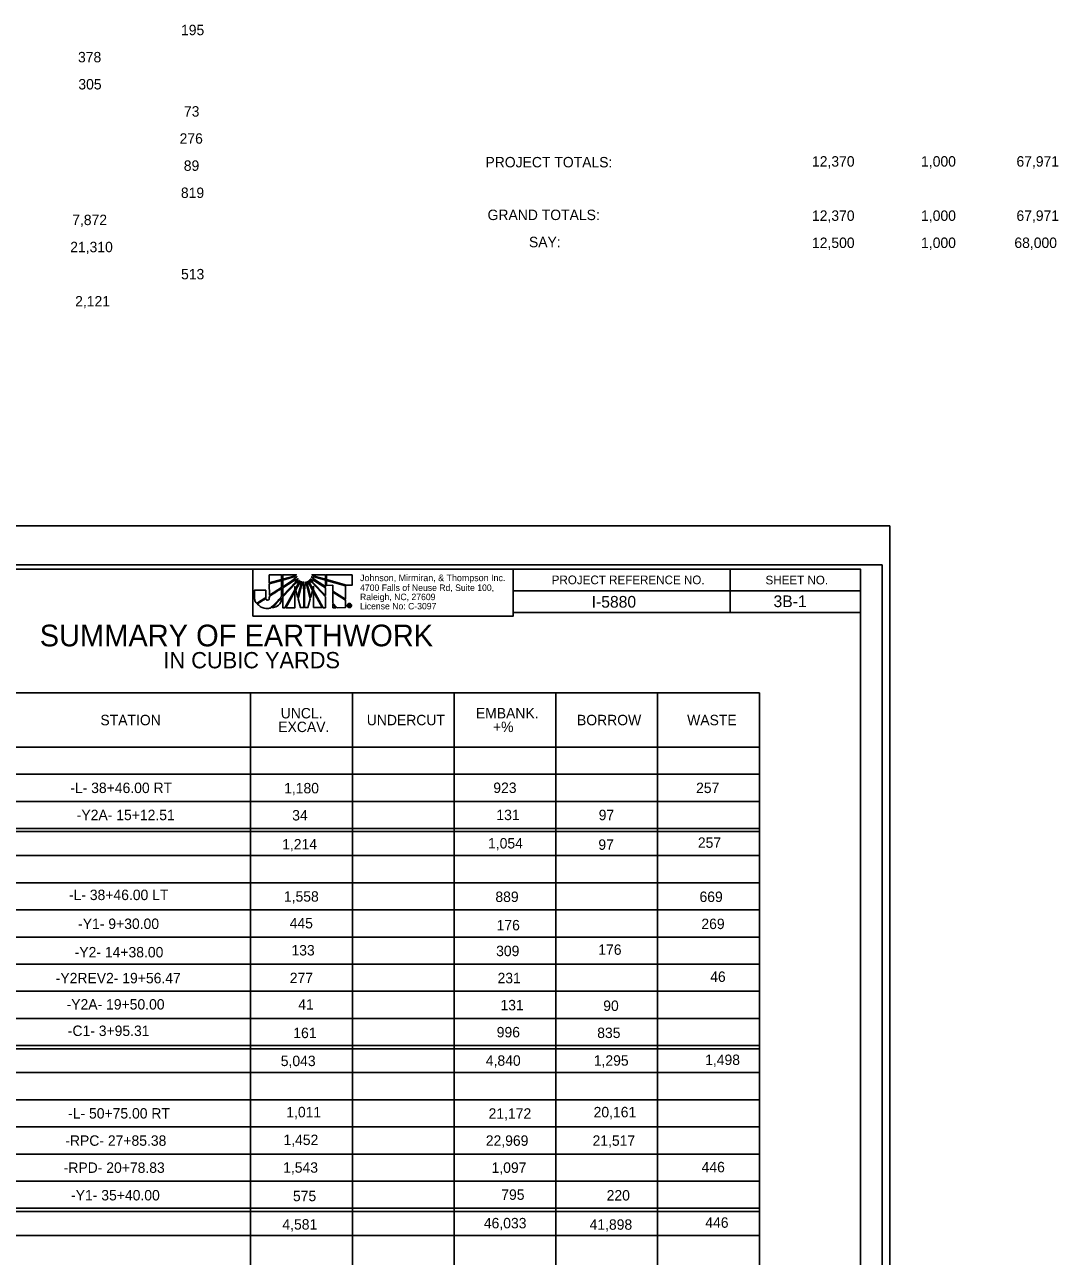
# Model space of a CAD drawing. Extents: x 573692 to 577281, y -53325 to -51406.
# Drawn here: x 574877 to 575473, y -52643 to -51934 of the extents above; entities that cross this region are included whole.
import ezdxf

# ---------------------------------------------------------------- set-up
doc = ezdxf.new("R2010")
doc.units = 0
for name, color, linetype in [('Exist Profile Cell', 7, 'Continuous'), ('Exist Vertical Profile Ground Line', 7, 'Continuous'), ('Prop Conc Island Cover', 7, 'Continuous'), ('Prop EOT', 7, 'Continuous'), ('Prop Horizontal Alignment', 7, 'Continuous'), ('Sheet North Arrow CELL', 7, 'Continuous')]:
    doc.layers.add(name, color=color, linetype=linetype)

msp = doc.modelspace()

# ---------------------------------------------------------------- linework, layer by layer
at = {"layer": 'Exist Profile Cell'}
msp.add_lwpolyline([(575375.82, -52222.48), (573691.82, -52222.48), (573691.82, -53322.48), (575375.82, -53322.48)], close=True, dxfattribs=at)
at = {"layer": 'Prop Conc Island Cover'}
msp.add_lwpolyline([(575371.32, -52244.93), (573704.82, -52244.93), (573704.82, -53300.03), (575371.32, -53300.03)], close=True, dxfattribs=at)
at = {"layer": 'Prop EOT'}
for p, q in [((575283.82, -52247.53), (575283.82, -52272.53)), ((575158.77, -52260.03), (575358.82, -52260.03)), ((575158.77, -52272.53), (575358.82, -52272.53)), ((574968.75, -52318.72), (574968.75, -52318.72)), ((574949.63, -52318.85), (574949.63, -52318.85)), ((574957.44, -52318.97), (574957.44, -52318.97)), ((574975.75, -52318.85), (574975.75, -52318.85))]:
    msp.add_line(p, q, dxfattribs=at)
for points in [[(575358.82, -52247.48), (573858.82, -52247.48), (573858.82, -53297.48), (575358.82, -53297.48)], [(575158.77, -52247.48), (575358.82, -52247.48), (575358.82, -52272.53), (575158.77, -52272.53)]]:
    msp.add_lwpolyline(points, close=True, dxfattribs=at)
at = {"layer": 'Prop Horizontal Alignment'}
for p, q in [((575025.33, -52250.8), (575018.31, -52250.8)), ((575018.31, -52250.8), (575018.31, -52255.46)), ((575018.31, -52255.46), (575025.33, -52253.51)), ((575025.33, -52254.02), (575018.31, -52255.99)), ((575025.33, -52253.51), (575025.33, -52250.8)), ((575025.33, -52258.08), (575025.33, -52254.02)), ((575033.95, -52250.75), (575026.06, -52250.76)), ((575026.06, -52250.76), (575026.06, -52253.27)), ((575026.06, -52253.27), (575031.94, -52251.65)), ((575031.94, -52252.19), (575026.06, -52253.82)), ((575026.06, -52253.82), (575026.06, -52257.62)), ((575026.06, -52257.62), (575031.33, -52254.28)), ((575032.14, -52254.36), (575026.06, -52258.23)), ((575026.07, -52262.61), (575033.46, -52254.9)), ((575031.33, -52254.28), (575034.23, -52251.91)), ((575031.94, -52251.65), (575033.95, -52250.75)), ((575034.23, -52251.91), (575031.94, -52252.19)), ((575034.81, -52253), (575032.14, -52254.36)), ((575033.46, -52254.9), (575034.81, -52253)), ((575035.62, -52253.84), (575033.76, -52255.28)), ((575034.77, -52256.09), (575035.62, -52253.84)), ((575036.63, -52254.47), (575035.24, -52256.25)), ((575036.44, -52256.63), (575036.63, -52254.47)), ((575037.79, -52254.78), (575036.83, -52257.03)), ((575038.1, -52260.32), (575037.79, -52254.78)), ((575038.95, -52254.78), (575038.6, -52260.31)), ((575039.88, -52257.02), (575038.95, -52254.78)), ((575040.07, -52254.47), (575040.31, -52256.71)), ((575041.43, -52256.25), (575040.07, -52254.47)), ((575041.07, -52253.84), (575041.93, -52256.08)), ((575042.93, -52255.27), (575041.07, -52253.84)), ((575041.89, -52252.99), (575043.25, -52254.93)), ((575044.6, -52254.35), (575041.89, -52252.99)), ((575042.5, -52251.9), (575045.44, -52254.31)), ((575044.67, -52252.18), (575042.5, -52251.9)), ((575050.68, -52250.77), (575042.89, -52250.75)), ((575042.89, -52250.75), (575044.86, -52251.67)), ((575043.25, -52254.93), (575050.64, -52262.67)), ((575050.64, -52258.17), (575044.6, -52254.35)), ((575050.68, -52253.83), (575044.67, -52252.18)), ((575044.86, -52251.67), (575050.68, -52253.3)), ((575045.44, -52254.31), (575050.64, -52257.55)), ((575050.64, -52257.55), (575050.68, -52253.83)), ((575050.68, -52253.3), (575050.68, -52250.77)), ((575065.97, -52250.72), (575051.22, -52250.74)), ((575051.22, -52250.74), (575051.22, -52253.45)), ((575051.22, -52253.45), (575051.22, -52253.53)), ((575051.22, -52253.53), (575062.84, -52256.77)), ((575051.22, -52253.95), (575051.22, -52253.99)), ((575062.1, -52257.04), (575051.22, -52253.95)), ((575051.22, -52253.99), (575051.23, -52256.82)), ((575065.98, -52256.77), (575065.97, -52250.72)), ((575018.31, -52255.99), (575018.32, -52262.53)), ((575018.32, -52262.53), (575025.33, -52258.08)), ((575026.06, -52258.23), (575026.07, -52262.61)), ((575033.76, -52255.28), (575026.07, -52263.35)), ((575027.23, -52269.72), (575032.95, -52259.35)), ((575032.96, -52260.35), (575027.78, -52269.72)), ((575032.95, -52259.35), (575032.95, -52257.49)), ((575032.95, -52257.49), (575033.3, -52258.77)), ((575033.01, -52269.71), (575032.96, -52260.35)), ((575033.3, -52258.77), (575034.77, -52256.09)), ((575035.24, -52256.25), (575033.5, -52259.43)), ((575033.5, -52259.43), (575034.63, -52263.64)), ((575034.63, -52263.64), (575036.44, -52256.63)), ((575036.83, -52257.03), (575034.86, -52264.61)), ((575038.11, -52269.67), (575038.1, -52260.32)), ((575038.6, -52260.31), (575038.6, -52269.67)), ((575041.9, -52264.72), (575039.88, -52257.02)), ((575040.31, -52256.71), (575042.13, -52263.8)), ((575043.25, -52259.53), (575041.43, -52256.25)), ((575041.93, -52256.08), (575043.43, -52258.87)), ((575042.13, -52263.8), (575043.25, -52259.53)), ((575050.64, -52263.39), (575042.93, -52255.27)), ((575043.43, -52258.87), (575043.79, -52257.48)), ((575043.79, -52257.48), (575043.79, -52259.53)), ((575043.79, -52259.53), (575049.41, -52269.7)), ((575048.83, -52269.66), (575043.79, -52260.54)), ((575043.79, -52260.54), (575043.8, -52269.67)), ((575050.64, -52262.67), (575050.64, -52258.17)), ((575051.23, -52256.82), (575054.83, -52256.81)), ((575054.83, -52256.81), (575054.83, -52260.18)), ((575054.83, -52260.18), (575062.11, -52264.79)), ((575054.83, -52260.76), (575054.84, -52267.04)), ((575062.11, -52265.33), (575054.83, -52260.76)), ((575062.11, -52264.79), (575062.1, -52257.04)), ((575062.84, -52256.77), (575065.98, -52256.77)), ((575026.07, -52263.35), (575026.07, -52269.72)), ((575034.86, -52264.61), (575036.18, -52269.67)), ((575040.55, -52269.67), (575041.9, -52264.72)), ((575050.65, -52269.69), (575050.64, -52263.39)), ((575054.84, -52267.04), (575057.35, -52269.69)), ((575056.66, -52269.69), (575054.84, -52267.72)), ((575054.84, -52267.72), (575054.84, -52269.69)), ((575062.11, -52269.68), (575062.11, -52265.33)), ((575063.96, -52269.02), (575063.96, -52267.95)), ((575063.96, -52267.95), (575064.4, -52267.95)), ((575064.2, -52269.02), (575063.96, -52269.02)), ((575064.4, -52268.15), (575064.2, -52268.15)), ((575064.2, -52268.15), (575064.2, -52268.4)), ((575064.2, -52268.4), (575064.4, -52268.4)), ((575064.4, -52268.6), (575064.2, -52268.6)), ((575064.2, -52268.6), (575064.2, -52269.02)), ((575064.4, -52267.31), (575064.4, -52267.54)), ((575064.4, -52267.54), (575064.4, -52267.31)), ((575064.4, -52267.95), (575064.4, -52268.15)), ((575064.4, -52268.15), (575064.4, -52267.95)), ((575064.4, -52267.95), (575064.46, -52267.95)), ((575064.43, -52268.15), (575064.4, -52268.15)), ((575064.4, -52268.4), (575064.4, -52268.6)), ((575064.4, -52268.6), (575064.4, -52268.4)), ((575064.4, -52268.4), (575064.41, -52268.4)), ((575064.41, -52268.6), (575064.4, -52268.6)), ((575026.07, -52269.72), (575027.23, -52269.72)), ((575027.78, -52269.72), (575033.01, -52269.71)), ((575036.18, -52269.67), (575038.11, -52269.67)), ((575038.6, -52269.67), (575040.55, -52269.67)), ((575043.8, -52269.67), (575048.83, -52269.66)), ((575049.41, -52269.7), (575050.65, -52269.69)), ((575054.84, -52269.69), (575056.66, -52269.69)), ((575057.35, -52269.69), (575062.11, -52269.68)), ((575064.4, -52269.44), (575064.4, -52269.67)), ((575064.4, -52269.67), (575064.4, -52269.44)), ((575064.4, -52269.44), (575064.41, -52269.44)), ((575064.41, -52269.67), (575064.4, -52269.67))]:
    msp.add_line(p, q, dxfattribs=at)
msp.add_lwpolyline([(575008.82, -52274.54), (575158.77, -52274.54), (575158.77, -52247.48), (575008.82, -52247.48)], close=True, dxfattribs=at)
for points in [[(575018.31, -52255.46), (575025.33, -52253.51), (575025.33, -52250.8), (575018.31, -52250.8), (575018.31, -52255.46)], [(575018.32, -52262.53), (575025.33, -52258.08), (575025.33, -52254.02), (575018.31, -52255.99), (575018.32, -52262.53)], [(575031.94, -52251.65), (575033.95, -52250.75), (575026.06, -52250.76), (575026.06, -52253.27), (575031.94, -52251.65)], [(575026.06, -52253.82), (575026.06, -52257.62), (575031.33, -52254.28), (575034.23, -52251.91), (575031.94, -52252.19), (575026.06, -52253.82)], [(575026.06, -52258.23), (575026.07, -52262.61), (575033.46, -52254.9), (575034.81, -52253), (575032.14, -52254.36), (575026.06, -52258.23)], [(575035.62, -52253.84), (575033.76, -52255.28), (575026.07, -52263.35), (575026.07, -52269.72), (575027.23, -52269.72), (575032.95, -52259.35), (575032.95, -52257.49), (575033.3, -52258.77), (575034.77, -52256.09), (575035.62, -52253.84)], [(575036.63, -52254.47), (575035.24, -52256.25), (575033.5, -52259.43), (575034.63, -52263.64), (575036.44, -52256.63), (575036.63, -52254.47)], [(575036.83, -52257.03), (575034.86, -52264.61), (575036.18, -52269.67), (575038.11, -52269.67), (575038.1, -52260.32), (575037.79, -52254.78), (575036.83, -52257.03)], [(575038.95, -52254.78), (575038.6, -52260.31), (575038.6, -52269.67), (575040.55, -52269.67), (575041.9, -52264.72), (575039.88, -52257.02), (575038.95, -52254.78)], [(575040.07, -52254.47), (575040.31, -52256.71), (575042.13, -52263.8), (575043.25, -52259.53), (575041.43, -52256.25), (575040.07, -52254.47)], [(575041.07, -52253.84), (575041.93, -52256.08), (575043.43, -52258.87), (575043.79, -52257.48), (575043.79, -52259.53), (575049.41, -52269.7), (575050.65, -52269.69), (575050.64, -52263.39), (575042.93, -52255.27), (575041.07, -52253.84)], [(575041.89, -52252.99), (575043.25, -52254.93), (575050.64, -52262.67), (575050.64, -52258.17), (575044.6, -52254.35), (575041.89, -52252.99)], [(575042.5, -52251.9), (575045.44, -52254.31), (575050.64, -52257.55), (575050.68, -52253.83), (575044.67, -52252.18), (575042.5, -52251.9)], [(575044.86, -52251.67), (575050.68, -52253.3), (575050.68, -52250.77), (575042.89, -52250.75), (575044.86, -52251.67)], [(575065.97, -52250.72), (575051.22, -52250.74), (575051.22, -52253.45), (575051.22, -52253.53), (575062.84, -52256.77), (575065.98, -52256.77), (575065.97, -52250.72)], [(575051.22, -52253.95), (575051.22, -52253.99), (575051.23, -52256.82), (575054.83, -52256.81), (575054.83, -52260.18), (575062.11, -52264.79), (575062.1, -52257.04), (575051.22, -52253.95)], [(575027.78, -52269.72), (575033.01, -52269.71), (575032.96, -52260.35), (575027.78, -52269.72)], [(575043.8, -52269.67), (575048.83, -52269.66), (575043.79, -52260.54), (575043.8, -52269.67)], [(575054.83, -52260.76), (575054.84, -52267.04), (575057.35, -52269.69), (575062.11, -52269.68), (575062.11, -52265.33), (575054.83, -52260.76), (575054.83, -52260.76)], [(575054.84, -52269.69), (575054.84, -52269.69), (575056.66, -52269.69), (575054.84, -52267.72), (575054.84, -52269.69)], [(575064.87, -52268.76), (575064.87, -52268.82), (575064.87, -52268.86), (575064.87, -52268.9), (575064.9, -52269.02), (575064.68, -52269.02)]]:
    msp.add_lwpolyline(points, dxfattribs=at)
for points, degree in [([(575016.3, -52259.53), (575016.3, -52259.53), (575009.81, -52259.53), (575009.81, -52259.53), (575009.81, -52259.53), (575009.81, -52263.6), (575009.81, -52263.6), (575009.81, -52263.6), (575009.81, -52264.02), (575009.81, -52264.02), (575009.81, -52265.3), (575010.23, -52266.31), (575010.97, -52267.15), (575010.97, -52267.15), (575016.31, -52263.9), (575016.31, -52263.82), (575016.31, -52263.82), (575016.3, -52259.53), (575016.3, -52259.53)], 3), ([(575017.32, -52265.37), (575016.9, -52265.37), (575016.54, -52265.14), (575016.39, -52264.37), (575016.39, -52264.37), (575011.35, -52267.49), (575011.35, -52267.49), (575012.91, -52269.12), (575015.39, -52270.09), (575017.48, -52270.08), (575018.03, -52270.08), (575018.44, -52270.04), (575019.02, -52269.92), (575019.02, -52269.92), (575025.34, -52263.38), (575025.34, -52263.38), (575025.34, -52263.38), (575025.33, -52258.66), (575025.33, -52258.66), (575025.33, -52258.66), (575018.32, -52263.12), (575018.32, -52263.12), (575018.32, -52264.9), (575017.9, -52265.37), (575017.32, -52265.37)], 3), ([(575017.32, -52265.37), (575016.9, -52265.37), (575016.54, -52265.14), (575016.39, -52264.37), (575016.39, -52264.37), (575011.35, -52267.49), (575011.35, -52267.49), (575012.91, -52269.12), (575015.39, -52270.09), (575017.48, -52270.08), (575018.03, -52270.08), (575018.44, -52270.04), (575019.02, -52269.92), (575019.02, -52269.92), (575025.34, -52263.38), (575025.34, -52263.38), (575025.34, -52263.38), (575025.33, -52258.66), (575025.33, -52258.66), (575025.33, -52258.66), (575018.32, -52263.12), (575018.32, -52263.12), (575018.32, -52264.9), (575017.9, -52265.37), (575017.32, -52265.37)], 3), ([(575025.34, -52264.13), (575025.34, -52264.13), (575019.88, -52269.77), (575019.88, -52269.77), (575022.55, -52269.11), (575025.22, -52267.33), (575025.34, -52264.13)], 3), ([(575064.4, -52269.67), (575064.08, -52269.67), (575063.79, -52269.56), (575063.56, -52269.32), (575063.32, -52269.1), (575063.21, -52268.82), (575063.21, -52268.48), (575063.21, -52268.15), (575063.32, -52267.87), (575063.56, -52267.65), (575063.79, -52267.43), (575064.06, -52267.31), (575064.4, -52267.31)], 3), ([(575064.4, -52267.54), (575064.13, -52267.54), (575063.91, -52267.62), (575063.72, -52267.8), (575063.54, -52267.99), (575063.44, -52268.22), (575063.44, -52268.48), (575063.44, -52268.75), (575063.54, -52268.98), (575063.72, -52269.17), (575063.91, -52269.35), (575064.13, -52269.44), (575064.4, -52269.44)], 3), ([(575064.4, -52267.31), (575064.73, -52267.31), (575065.01, -52267.43), (575065.24, -52267.65), (575065.48, -52267.87), (575065.6, -52268.15), (575065.6, -52268.48)], 3), ([(575064.41, -52269.44), (575064.67, -52269.44), (575064.89, -52269.35), (575065.08, -52269.16), (575065.27, -52268.98), (575065.36, -52268.74), (575065.36, -52268.48), (575065.36, -52268.22), (575065.26, -52267.98), (575065.08, -52267.8), (575064.89, -52267.62), (575064.67, -52267.54), (575064.4, -52267.54)], 3), ([(575064.41, -52268.4), (575064.56, -52268.4), (575064.64, -52268.36), (575064.64, -52268.27), (575064.64, -52268.19), (575064.57, -52268.15), (575064.43, -52268.15)], 3), ([(575065.6, -52268.48), (575065.6, -52268.81), (575065.48, -52269.1), (575065.26, -52269.33), (575065.02, -52269.55), (575064.74, -52269.67), (575064.41, -52269.67)], 3), ([(575064.59, -52268.64), (575064.56, -52268.62), (575064.5, -52268.6), (575064.41, -52268.6)], 2), ([(575064.46, -52267.95), (575064.74, -52267.95), (575064.87, -52268.05), (575064.87, -52268.27), (575064.87, -52268.36), (575064.84, -52268.44), (575064.75, -52268.5)], 3), ([(575064.68, -52269.02), (575064.65, -52268.96), (575064.63, -52268.9), (575064.63, -52268.82), (575064.63, -52268.73), (575064.62, -52268.67), (575064.59, -52268.64)], 3), ([(575064.75, -52268.5), (575064.82, -52268.54), (575064.86, -52268.63), (575064.87, -52268.76)], 2)]:
    msp.add_open_spline(points, degree=degree, dxfattribs=at)
at = {"layer": 'Sheet North Arrow CELL'}
for p, q in [((574726, -52318.78), (575300.63, -52318.78)), ((575007.5, -52318.78), (575007.5, -52865.43)), ((575066.13, -52318.78), (575066.13, -52865.43)), ((575124.75, -52318.78), (575124.75, -52865.43)), ((575183.38, -52318.78), (575183.38, -52865.43)), ((575242, -52318.78), (575242, -52865.43)), ((575300.63, -52318.78), (575300.63, -52865.43)), ((574725.96, -52350.03), (575300.63, -52350.03)), ((574726, -52365.66), (575300.63, -52365.66)), ((574726, -52381.28), (575300.63, -52381.28)), ((574726, -52396.91), (575300.63, -52396.91)), ((574726, -52398.7), (575300.63, -52398.7)), ((574726, -52412.53), (575300.63, -52412.53)), ((574726, -52428.16), (575300.63, -52428.16)), ((574726, -52443.78), (575300.63, -52443.78)), ((574726, -52459.41), (575300.63, -52459.41)), ((574726, -52475.03), (575300.63, -52475.03)), ((574726, -52490.66), (575300.63, -52490.66)), ((574726, -52506.28), (575300.63, -52506.28)), ((574726, -52521.91), (575300.63, -52521.91)), ((574726, -52523.71), (575300.63, -52523.71)), ((574726, -52537.53), (575300.63, -52537.53)), ((574726, -52553.16), (575300.63, -52553.16)), ((574726, -52568.78), (575300.63, -52568.78)), ((574726, -52584.41), (575300.63, -52584.41)), ((574726, -52600.03), (575300.63, -52600.03)), ((574726, -52615.66), (575300.63, -52615.66)), ((574726, -52617.47), (575300.63, -52617.47)), ((574726, -52631.23), (575300.63, -52631.23))]:
    msp.add_line(p, q, dxfattribs=at)

# ---------------------------------------------------------------- texts
at = {"layer": 'Exist Vertical Profile Ground Line'}
for s, p in [('I-5880', (575203.99, -52269.68)), ('3B-1', (575308.75, -52269.38))]:
    msp.add_text(s, height=6.75, dxfattribs=at).set_placement(p)
at = {"layer": 'Prop EOT'}
for s, height, p in [('195', 6, (574967.45, -51939.93)), ('378', 6, (574908.12, -51955.56)), ('305', 6, (574908.31, -51971.18)), ('73', 6, (574969.13, -51986.81)), ('276', 6, (574966.64, -52002.43)), ('89', 6, (574969.04, -52018.06)), ('PROJECT TOTALS:', 6, (575142.8, -52016.06)), ('12,370', 6, (575330.89, -52015.62)), ('1,000', 6, (575393.73, -52015.62)), ('67,971', 6, (575448.66, -52015.62)), ('819', 6, (574967.39, -52033.68)), ('GRAND TOTALS:', 6, (575144.03, -52046.42)), ('12,370', 6, (575330.89, -52046.87)), ('1,000', 6, (575393.73, -52046.87)), ('67,971', 6, (575448.66, -52046.87)), ('7,872', 6, (574904.76, -52049.31)), ('SAY:', 6, (575167.86, -52062.05)), ('21,310', 6, (574903.62, -52064.93)), ('12,500', 6, (575330.89, -52062.49)), ('1,000', 6, (575393.73, -52062.49)), ('68,000', 6, (575447.47, -52062.49)), ('513', 6, (574967.46, -52080.56)), ('2,121', 6, (574906.46, -52096.18)), ('PROJECT REFERENCE NO.', 5.0001, (575180.97, -52256.18)), ('SHEET NO.', 5, (575304.12, -52256.28)), ('STATION', 6, (574921.02, -52337.41)), ('UNCL.', 6, (575024.89, -52333.47)), ('UNDERCUT', 6, (575074.45, -52337.41)), ('EMBANK.', 6, (575137.29, -52333.47)), ('BORROW', 6, (575195.53, -52337.41)), ('WASTE', 6, (575258.98, -52337.41)), ('EXCAV.', 6, (575023.45, -52341.35)), ('+%', 6, (575147.14, -52341.35)), ('-L- 38+46.00 RT', 6, (574903.67, -52376.47)), ('1,180', 6, (575026.84, -52376.64)), ('923', 6, (575147.33, -52376.43)), ('257', 6, (575264.14, -52376.47)), ('-Y2A- 15+12.51', 6, (574907.41, -52392.1)), ('34', 6, (575031.5, -52392.27)), ('131', 6, (575149.1, -52392.06)), ('97', 6, (575208.03, -52392.1)), ('1,214', 6, (575025.69, -52408.98)), ('1,054', 6, (575144.29, -52408.4)), ('97', 6, (575207.85, -52409.16)), ('257', 6, (575265.16, -52408.02)), ('-L- 38+46.00 LT', 6, (574902.88, -52438.12)), ('1,558', 6, (575026.72, -52439.03)), ('889', 6, (575148.53, -52439.22)), ('669', 6, (575266.11, -52439.22)), ('-Y1- 9+30.00', 6, (574908.19, -52454.77)), ('445', 6, (575030.04, -52454.43)), ('176', 6, (575149.24, -52455.57)), ('269', 6, (575267.18, -52454.81)), ('-Y2- 14+38.00', 6, (574906.2, -52471.13)), ('133', 6, (575031.07, -52470.03)), ('309', 6, (575148.95, -52470.41)), ('176', 6, (575207.8, -52469.65)), ('-Y2REV2- 19+56.47', 6, (574895.28, -52486.05)), ('277', 6, (575030.09, -52485.96)), ('231', 6, (575149.78, -52486.01)), ('46', 6, (575272.25, -52485.25)), ('-Y2A- 19+50.00', 6, (574901.54, -52501.18)), ('41', 6, (575034.99, -52501.22)), ('131', 6, (575151.44, -52501.6)), ('90', 6, (575210.65, -52501.98)), ('-C1- 3+95.31', 6, (574902.24, -52516.4)), ('161', 6, (575032.13, -52517.62)), ('996', 6, (575149.29, -52517.2)), ('835', 6, (575207.19, -52517.58)), ('5,043', 6, (575024.9, -52533.75)), ('4,840', 6, (575143.02, -52533.55)), ('1,295', 6, (575205.2, -52533.5)), ('1,498', 6, (575269.34, -52533.12)), ('-L- 50+75.00 RT', 6, (574902.42, -52563.96)), ('1,011', 6, (575028.1, -52563.25)), ('21,172', 6, (575144.62, -52564.05)), ('20,161', 6, (575205.11, -52563.25)), ('-RPC- 27+85.38', 6, (574900.8, -52579.65)), ('1,452', 6, (575026.46, -52579.22)), ('22,969', 6, (575143.01, -52579.65)), ('21,517', 6, (575204.51, -52579.65)), ('-RPD- 20+78.83', 6, (574899.88, -52595.24)), ('1,543', 6, (575026.27, -52595.16)), ('1,097', 6, (575146.34, -52595.24)), ('446', 6, (575267.31, -52594.92)), ('-Y1- 35+40.00', 6, (574904.14, -52611.12)), ('575', 6, (575031.93, -52611.56)), ('795', 6, (575151.92, -52610.8)), ('220', 6, (575212.63, -52611.18)), ('4,581', 6, (575025.84, -52627.93)), ('46,033', 6, (575141.89, -52627.2)), ('41,898', 6, (575202.79, -52628.01)), ('446', 6, (575269.43, -52626.87))]:
    msp.add_text(s, height=height, dxfattribs=at).set_placement(p)
for s, height, p in [('SUMMARY OF EARTHWORK', 12.5001, (574886.06, -52291.98)), ('IN CUBIC YARDS', 9.3751, (574957.31, -52304.62))]:
    msp.add_text(s, height=height, rotation=0.01193, dxfattribs=at).set_placement(p)
at = {"layer": 'Prop Horizontal Alignment'}
for s, height, p in [('Johnson, Mirmiran, & Thompson Inc.', 3.8315, (575070.57, -52254.41)), ('4700 Falls of Neuse Rd, Suite 100, ', 3.722, (575070.57, -52260.04)), ('Raleigh, NC, 27609', 3.722, (575070.57, -52265.35)), ('License No: C-3097', 3.722, (575070.57, -52270.67))]:
    msp.add_text(s, height=height, rotation=360, dxfattribs=at).set_placement(p)

doc.saveas('drawing.dxf')
